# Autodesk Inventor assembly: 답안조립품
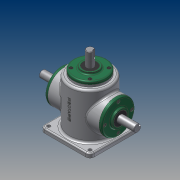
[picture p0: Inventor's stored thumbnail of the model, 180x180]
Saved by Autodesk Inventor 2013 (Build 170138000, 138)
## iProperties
Created: 2015-10
Part Number: 답안조립품
Document SubType Name: Assembly
Designer: Administrator
Author: Administrator
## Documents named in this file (14)
- C:\Users\Administrator\Desktop\451008V1020\답안조립품.iam
- C:\Users\Administrator\Desktop\451008V1020\본체.ipt
- C:\Users\Administrator\Desktop\451008V1020\M4.ipt
- C:\Users\Administrator\Desktop\451008V1020\메인 베벨기어.ipt
- C:\Users\Administrator\Desktop\451008V1020\메인 축.ipt
- 메인 축.ipt
- C:\Users\Administrator\Desktop\451008V1020\베어링 6203.ipt
- C:\Users\Administrator\Desktop\451008V1020\서브 베벨기어.ipt
- C:\Users\Administrator\Desktop\451008V1020\서브 축.ipt
- 서브 축.ipt
- C:\Users\Administrator\Desktop\451008V1020\오일실.ipt
- C:\Users\Administrator\Desktop\451008V1020\커버.ipt
- C:\Users\Administrator\Desktop\451008V1020\키 4x4.ipt
- C:\Users\Administrator\Desktop\451008V1020\키 5x5.ipt
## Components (12 placed, 1 different names)
1. M4:1 — 각도:10
2. M4:5
3. M4:6
4. M4:7
5. M4:4 — 각도:9
6. M4:8
7. M4:9
8. M4:10
9. M4:3 — 각도:8
10. M4:11
11. M4:12
12. M4:13
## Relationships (3: Angle 3)
- 각도:8 [Angle]: M4:3
- 각도:9 [Angle]: M4:4
- 각도:10 [Angle]: M4:1
